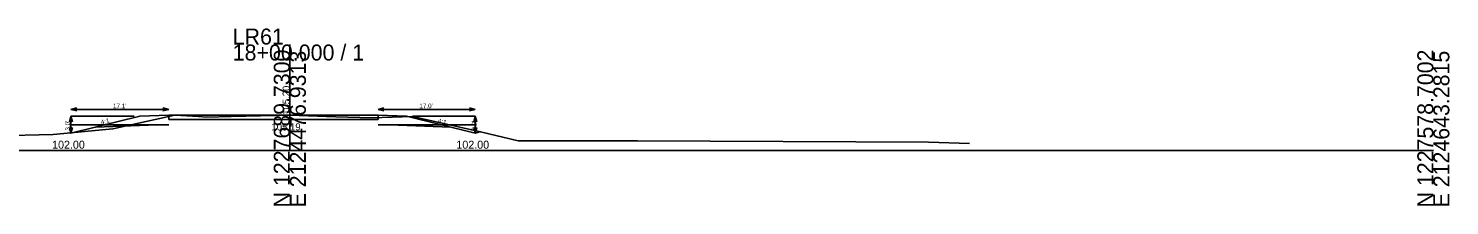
# Model space of a CAD drawing. Extents: x -26 to 1403, y -10 to 9574.
# Drawn here: x 1154.3 to 1402.8, y 7990.3 to 8021.4 of the extents above; entities that cross this region are included whole.
import ezdxf

# ---------------------------------------------------------------- set-up
doc = ezdxf.new("R2010")
doc.units = 0
for name, color, linetype in [('XS_CELL', 7, 'Continuous'), ('XS_P_FINISHED_GRADE', 7, 'Continuous'), ('XS_P_FINISHED_GRADE_ELEV_TX', 7, 'Continuous'), ('XS_P_SUBGRADE_GRANULAR', 7, 'Continuous'), ('XS_P_SUBGRADE_PAVEMENT', 7, 'Continuous'), ('XS_P_TX_CLEARZONE', 7, 'Continuous'), ('XS_P_TX_DCH', 7, 'Continuous'), ('XS_P_TX_FS_BS', 7, 'Continuous'), ('XS_X_GROUND', 7, 'Continuous'), ('XS_X_GROUND_TX', 7, 'Continuous')]:
    doc.layers.add(name, color=color, linetype=linetype)

msp = doc.modelspace()

# ---------------------------------------------------------------- linework, layer by layer
at = {"layer": 'XS_CELL'}
for p, q in [((1200, 8000), (1200, 8018.57)), ((1000, 8000), (1200, 8000)), ((1200, 8000), (1400, 8000))]:
    msp.add_line(p, q, dxfattribs=at)
at = {"layer": 'XS_P_FINISHED_GRADE'}
for p, q in [((1178.81, 8006.2), (1173.78, 8006)), ((1200, 8006.2), (1178.81, 8006.2)), ((1200, 8006.2), (1215.43, 8006.2)), ((1215.43, 8006.2), (1220.43, 8006)), ((1173.78, 8006), (1161.72, 8003)), ((1220.43, 8006), (1232.43, 8003)), ((1161.72, 8003), (1161.53, 8003.06)), ((1232.43, 8003), (1233.26, 8003.27))]:
    msp.add_line(p, q, dxfattribs=at)
at = {"layer": 'XS_P_SUBGRADE_GRANULAR'}
for p, q in [((1161.52, 8004.5), (1178.81, 8004.5)), ((1176.81, 8004.5), (1166.02, 8004.06)), ((1178.81, 8004.5), (1176.81, 8004.5)), ((1232.63, 8004.5), (1215.43, 8004.5)), ((1215.43, 8004.5), (1217.43, 8004.5)), ((1217.43, 8004.5), (1228.15, 8004.07))]:
    msp.add_line(p, q, dxfattribs=at)
at = {"layer": 'XS_P_SUBGRADE_PAVEMENT'}
for p, q in [((1178.81, 8005.45), (1178.81, 8006.2)), ((1215.43, 8005.45), (1215.43, 8006.2)), ((1200, 8005.45), (1178.81, 8005.45)), ((1200, 8005.45), (1215.43, 8005.45))]:
    msp.add_line(p, q, dxfattribs=at)
at = {"layer": 'XS_P_TX_CLEARZONE'}
for p, q in [((1161.72, 8007.2), (1162.73, 8007.45)), ((1161.72, 8007.2), (1162.73, 8006.95)), ((1178.81, 8007.2), (1161.72, 8007.2)), ((1178.81, 8007.2), (1177.8, 8007.45)), ((1178.81, 8007.2), (1177.8, 8006.95)), ((1215.43, 8007.2), (1216.43, 8007.45)), ((1215.43, 8007.2), (1216.43, 8006.95)), ((1215.43, 8007.2), (1232.43, 8007.2)), ((1232.43, 8007.2), (1231.43, 8007.45)), ((1232.43, 8007.2), (1231.43, 8006.95)), ((1161.72, 8006), (1161.47, 8005)), ((1161.72, 8003), (1161.47, 8004)), ((1161.72, 8006), (1161.97, 8005)), ((1161.72, 8006), (1161.72, 8003)), ((1172.78, 8006), (1161.72, 8006)), ((1161.72, 8003), (1161.97, 8004)), ((1221.43, 8006), (1232.43, 8006)), ((1232.43, 8006), (1232.18, 8005)), ((1232.43, 8003), (1232.18, 8004)), ((1232.43, 8006), (1232.43, 8003)), ((1232.43, 8006), (1232.68, 8005)), ((1232.43, 8003), (1232.68, 8004))]:
    msp.add_line(p, q, dxfattribs=at)
at = {"layer": 'XS_X_GROUND'}
for p, q in [((1169.02, 8003.78), (1179.89, 8006.19)), ((1179.89, 8006.19), (1184.04, 8005.93)), ((1189.76, 8005.95), (1199.98, 8006.19)), ((1199.98, 8006.19), (1208.02, 8005.91)), ((1158.61, 8002.78), (1169.02, 8003.78)), ((1184.04, 8005.93), (1185.5, 8005.85)), ((1185.5, 8005.85), (1189.76, 8005.95)), ((1208.02, 8005.91), (1214.32, 8005.7)), ((1214.32, 8005.7), (1217.92, 8005.83)), ((1217.92, 8005.83), (1221.45, 8005.96)), ((1221.45, 8005.96), (1233.37, 8003.25)), ((1126.32, 8001.97), (1158.61, 8002.78)), ((1233.37, 8003.25), (1239.95, 8001.69)), ((1239.95, 8001.69), (1260.83, 8001.68)), ((1260.83, 8001.68), (1311.73, 8001.47)), ((1311.73, 8001.47), (1318.87, 8001.24))]:
    msp.add_line(p, q, dxfattribs=at)

# ---------------------------------------------------------------- texts
at = {"layer": 'XS_CELL'}
for s, p in [('LR61', (1190, 8018.57)), ('18+00.000 / 1', (1190, 8015.77))]:
    msp.add_text(s, height=2.8, dxfattribs=at).set_placement(p)
for s, p in [('N 1227689.7300', (1200, 7990)), ('E 2124476.9313', (1202.8, 7990)), ('N 1227578.7002', (1400, 7990)), ('E 2124643.2815', (1402.8, 7990))]:
    msp.add_text(s, height=2.8, rotation=90, dxfattribs=at).set_placement(p)
at = {"layer": 'XS_P_FINISHED_GRADE_ELEV_TX'}
msp.add_text('105.20.', height=1.25, rotation=90, dxfattribs=at).set_placement((1199.98, 8006.24))
at = {"layer": 'XS_P_TX_CLEARZONE'}
for s, p in [("17.1'", (1169.07, 8007.4)), ("17.0'", (1222.65, 8007.4))]:
    msp.add_text(s, height=0.8, dxfattribs=at).set_placement(p)
for p in [(1161.52, 8003.47), (1232.63, 8003.47)]:
    msp.add_text("3.0'", height=0.8, rotation=90, dxfattribs=at).set_placement(p)
at = {"layer": 'XS_P_TX_DCH'}
for p in [(1158.42, 8000.3), (1229.13, 8000.3)]:
    msp.add_text('102.00', height=1.4, dxfattribs=at).set_placement(p)
at = {"layer": 'XS_P_TX_FS_BS'}
for rotation, p in [(13.9701, (1167.04, 8004.53)), (345.9674, (1225.82, 8004.86))]:
    msp.add_text('4:1', height=0.8, rotation=rotation, dxfattribs=at).set_placement(p)
at = {"layer": 'XS_X_GROUND_TX'}
msp.add_text('105.19', height=1.25, rotation=360, dxfattribs=at).set_placement((1196.77, 8003.5))

doc.saveas('drawing.dxf')
